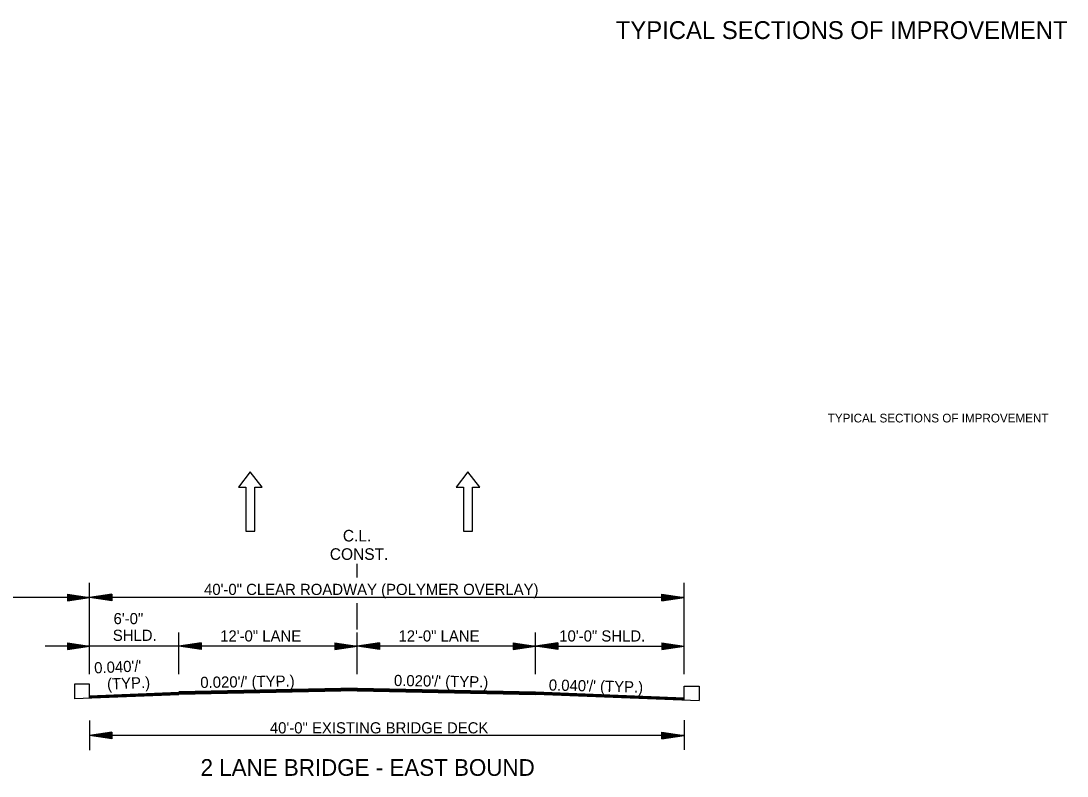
# Model space of a CAD drawing. Extents: x 550980 to 1930787, y -1972975 to 596640.
# Drawn here: x 551842 to 552546, y -1962178 to -1961670 of the extents above; entities that cross this region are included whole.
import ezdxf

# ---------------------------------------------------------------- set-up
doc = ezdxf.new("R2010")
doc.units = 0
for name, color, linetype in [('R_Border', 7, 'Continuous'), ('R_Draft', 7, 'Continuous'), ('S_AREA_CALC', 7, 'Continuous')]:
    doc.layers.add(name, color=color, linetype=linetype)

msp = doc.modelspace()

# ---------------------------------------------------------------- linework, layer by layer
at = {"layer": 'R_Border'}
for p, q in [((551878.08, -1962116.31), (551878.08, -1962126.13)), ((551888.24, -1962116.31), (551878.08, -1962116.31)), ((551888.24, -1962125.72), (551888.24, -1962116.31)), ((552288.24, -1962126.92), (552288.24, -1962117.51)), ((552288.24, -1962117.51), (552298.41, -1962117.51)), ((552298.41, -1962117.51), (552298.41, -1962127.33))]:
    msp.add_line(p, q, dxfattribs=at)
for points in [[(552004.34, -1961983.77), (551996.34, -1961973.39), (551988.34, -1961983.77), (551993.34, -1961983.77), (551993.34, -1962013.2), (551999.34, -1962013.2), (551999.34, -1961983.77)], [(552150.79, -1961983.77), (552142.79, -1961973.39), (552134.79, -1961983.77), (552139.79, -1961983.77), (552139.79, -1962013.2), (552145.79, -1962013.2), (552145.79, -1961983.77)]]:
    msp.add_lwpolyline(points, close=True, dxfattribs=at)
at = {"layer": 'R_Draft'}
for p, q in [((552068.24, -1962044.46), (552068.24, -1962035.16)), ((551888.24, -1962109.47), (551888.24, -1962047.98)), ((552288.24, -1962109.47), (552288.24, -1962047.98)), ((551873.24, -1962055.63), (551888.24, -1962057.88)), ((551873.24, -1962055.63), (551873.24, -1962060.13)), ((551903.24, -1962055.63), (551888.24, -1962057.88)), ((551903.24, -1962055.63), (551903.24, -1962060.13)), ((552273.24, -1962055.63), (552288.24, -1962057.88)), ((552273.24, -1962060.13), (552273.24, -1962055.63)), ((551888.24, -1962057.88), (551548.24, -1962057.88)), ((551873.24, -1962056), (551885.74, -1962057.88)), ((551873.24, -1962056.38), (551883.16, -1962057.88)), ((551873.24, -1962056.76), (551880.66, -1962057.88)), ((551873.24, -1962057.15), (551878.12, -1962057.88)), ((551873.24, -1962057.52), (551875.61, -1962057.88)), ((551873.24, -1962060.13), (551888.24, -1962057.88)), ((551873.24, -1962058.61), (551878.12, -1962057.88)), ((551873.24, -1962059.37), (551883.16, -1962057.88)), ((551873.24, -1962059.75), (551885.74, -1962057.88)), ((551873.24, -1962058.99), (551880.66, -1962057.88)), ((551873.24, -1962058.23), (551875.61, -1962057.88)), ((552288.24, -1962057.88), (551888.24, -1962057.88)), ((551903.24, -1962060.13), (551888.24, -1962057.88)), ((551903.24, -1962056), (551890.75, -1962057.88)), ((551903.24, -1962059.75), (551890.75, -1962057.88)), ((551903.24, -1962056.38), (551893.33, -1962057.88)), ((551903.24, -1962059.37), (551893.33, -1962057.88)), ((551903.24, -1962056.76), (551895.83, -1962057.88)), ((551903.24, -1962058.99), (551895.83, -1962057.88)), ((551903.24, -1962057.15), (551898.37, -1962057.88)), ((551903.24, -1962058.61), (551898.37, -1962057.88)), ((551903.24, -1962057.52), (551900.87, -1962057.88)), ((551903.24, -1962058.23), (551900.87, -1962057.88)), ((552258.24, -1962057.88), (551978.24, -1962057.88)), ((552068.24, -1962079.4), (552068.24, -1962061.64)), ((552273.24, -1962056), (552285.74, -1962057.88)), ((552273.24, -1962056.38), (552283.16, -1962057.88)), ((552273.24, -1962056.76), (552280.66, -1962057.88)), ((552273.24, -1962057.14), (552278.12, -1962057.88)), ((552273.24, -1962057.52), (552275.61, -1962057.88)), ((552273.24, -1962060.13), (552288.24, -1962057.88)), ((552273.24, -1962058.6), (552278.12, -1962057.88)), ((552273.24, -1962059.37), (552283.16, -1962057.88)), ((552273.24, -1962059.75), (552285.74, -1962057.88)), ((552273.24, -1962058.99), (552280.66, -1962057.88)), ((552273.24, -1962058.23), (552275.61, -1962057.88)), ((551948.24, -1962109.47), (551948.24, -1962081.52)), ((552068.24, -1962109.47), (552068.24, -1962081.52)), ((552188.24, -1962109.47), (552188.24, -1962081.52)), ((551888.24, -1962090.71), (551858.24, -1962090.71)), ((551873.24, -1962088.46), (551888.24, -1962090.71)), ((551873.24, -1962088.46), (551873.24, -1962092.96)), ((551873.24, -1962088.84), (551885.74, -1962090.71)), ((551873.24, -1962089.22), (551883.16, -1962090.71)), ((551873.24, -1962089.59), (551880.66, -1962090.71)), ((551873.24, -1962089.98), (551878.12, -1962090.71)), ((551873.24, -1962090.36), (551875.61, -1962090.71)), ((551873.24, -1962092.96), (551888.24, -1962090.71)), ((551873.24, -1962091.45), (551878.12, -1962090.71)), ((551873.24, -1962092.2), (551883.16, -1962090.71)), ((551873.24, -1962092.59), (551885.74, -1962090.71)), ((551873.24, -1962091.83), (551880.66, -1962090.71)), ((551873.24, -1962091.06), (551875.61, -1962090.71)), ((551948.24, -1962090.71), (551888.24, -1962090.71)), ((551963.24, -1962088.46), (551948.24, -1962090.71)), ((552068.24, -1962090.71), (551948.24, -1962090.71)), ((551963.24, -1962092.96), (551948.24, -1962090.71)), ((551963.24, -1962088.84), (551950.75, -1962090.71)), ((551963.24, -1962092.59), (551950.75, -1962090.71)), ((551963.24, -1962089.22), (551953.33, -1962090.71)), ((551963.24, -1962092.2), (551953.33, -1962090.71)), ((551963.24, -1962089.59), (551955.83, -1962090.71)), ((551963.24, -1962091.83), (551955.83, -1962090.71)), ((551963.24, -1962089.98), (551958.37, -1962090.71)), ((551963.24, -1962091.45), (551958.37, -1962090.71)), ((551963.24, -1962090.36), (551960.87, -1962090.71)), ((551963.24, -1962091.06), (551960.87, -1962090.71)), ((551963.24, -1962088.46), (551963.24, -1962092.96)), ((552053.24, -1962088.46), (552068.24, -1962090.71)), ((552053.24, -1962088.46), (552053.24, -1962092.96)), ((552053.24, -1962088.84), (552065.74, -1962090.71)), ((552053.24, -1962089.22), (552063.16, -1962090.71)), ((552053.24, -1962089.59), (552060.66, -1962090.71)), ((552053.24, -1962089.98), (552058.12, -1962090.71)), ((552053.24, -1962090.36), (552055.61, -1962090.71)), ((552053.24, -1962092.96), (552068.24, -1962090.71)), ((552053.24, -1962091.45), (552058.12, -1962090.71)), ((552053.24, -1962092.2), (552063.16, -1962090.71)), ((552053.24, -1962092.59), (552065.74, -1962090.71)), ((552053.24, -1962091.83), (552060.66, -1962090.71)), ((552053.24, -1962091.06), (552055.61, -1962090.71)), ((552083.24, -1962088.46), (552068.24, -1962090.71)), ((552188.24, -1962090.71), (552068.24, -1962090.71)), ((552083.24, -1962092.96), (552068.24, -1962090.71)), ((552083.24, -1962088.84), (552070.75, -1962090.71)), ((552083.24, -1962092.59), (552070.75, -1962090.71)), ((552083.24, -1962089.22), (552073.33, -1962090.71)), ((552083.24, -1962092.2), (552073.33, -1962090.71)), ((552083.24, -1962089.59), (552075.83, -1962090.71)), ((552083.24, -1962091.83), (552075.83, -1962090.71)), ((552083.24, -1962089.98), (552078.37, -1962090.71)), ((552083.24, -1962091.45), (552078.37, -1962090.71)), ((552083.24, -1962090.36), (552080.87, -1962090.71)), ((552083.24, -1962091.06), (552080.87, -1962090.71)), ((552083.24, -1962088.46), (552083.24, -1962092.96)), ((552173.24, -1962088.46), (552188.24, -1962090.71)), ((552173.24, -1962088.46), (552173.24, -1962092.96)), ((552173.24, -1962088.84), (552185.74, -1962090.71)), ((552173.24, -1962089.22), (552183.16, -1962090.71)), ((552173.24, -1962089.59), (552180.66, -1962090.71)), ((552173.24, -1962089.98), (552178.12, -1962090.71)), ((552173.24, -1962090.36), (552175.61, -1962090.71)), ((552173.24, -1962092.96), (552188.24, -1962090.71)), ((552173.24, -1962091.45), (552178.12, -1962090.71)), ((552173.24, -1962092.2), (552183.16, -1962090.71)), ((552173.24, -1962092.59), (552185.74, -1962090.71)), ((552173.24, -1962091.83), (552180.66, -1962090.71)), ((552173.24, -1962091.06), (552175.61, -1962090.71)), ((552203.24, -1962088.46), (552188.24, -1962090.71)), ((552188.24, -1962090.71), (552288.24, -1962090.71)), ((552203.24, -1962092.96), (552188.24, -1962090.71)), ((552203.24, -1962088.84), (552190.75, -1962090.71)), ((552203.24, -1962092.59), (552190.75, -1962090.71)), ((552203.24, -1962089.22), (552193.33, -1962090.71)), ((552203.24, -1962092.2), (552193.33, -1962090.71)), ((552203.24, -1962089.59), (552195.83, -1962090.71)), ((552203.24, -1962091.83), (552195.83, -1962090.71)), ((552203.24, -1962089.98), (552198.37, -1962090.71)), ((552203.24, -1962091.45), (552198.37, -1962090.71)), ((552203.24, -1962090.36), (552200.87, -1962090.71)), ((552203.24, -1962091.06), (552200.87, -1962090.71)), ((552203.24, -1962088.46), (552203.24, -1962092.96)), ((552273.24, -1962088.46), (552288.24, -1962090.71)), ((552273.24, -1962088.46), (552273.24, -1962092.96)), ((552273.24, -1962088.84), (552285.74, -1962090.71)), ((552273.24, -1962089.22), (552283.16, -1962090.71)), ((552273.24, -1962089.59), (552280.66, -1962090.71)), ((552273.24, -1962089.98), (552278.12, -1962090.71)), ((552273.24, -1962090.36), (552275.61, -1962090.71)), ((552273.24, -1962092.96), (552288.24, -1962090.71)), ((552273.24, -1962091.45), (552278.12, -1962090.71)), ((552273.24, -1962092.2), (552283.16, -1962090.71)), ((552273.24, -1962092.59), (552285.74, -1962090.71)), ((552273.24, -1962091.83), (552280.66, -1962090.71)), ((552273.24, -1962091.06), (552275.61, -1962090.71)), ((552068.24, -1962119.02), (551948.24, -1962121.42)), ((552068.24, -1962119.02), (552188.24, -1962121.42)), ((551948.24, -1962123.32), (551878.08, -1962126.13)), ((551948.24, -1962121.82), (551888.24, -1962124.22)), ((551948.24, -1962122.12), (551888.24, -1962124.52)), ((551948.24, -1962122.42), (551888.24, -1962124.82)), ((551948.24, -1962122.72), (551888.24, -1962125.12)), ((551948.24, -1962123.02), (551888.24, -1962125.42)), ((552068.24, -1962119.32), (551948.24, -1962121.72)), ((552068.24, -1962119.62), (551948.24, -1962122.02)), ((552068.24, -1962119.92), (551948.24, -1962122.32)), ((552068.24, -1962120.22), (551948.24, -1962122.62)), ((552068.24, -1962120.52), (551948.24, -1962122.92)), ((552068.24, -1962120.69), (551948.24, -1962123.09)), ((552068.24, -1962119.32), (552188.24, -1962121.72)), ((552068.24, -1962119.62), (552188.24, -1962122.02)), ((552068.24, -1962119.92), (552188.24, -1962122.32)), ((552068.24, -1962120.22), (552188.24, -1962122.62)), ((552068.24, -1962120.52), (552188.24, -1962122.92)), ((552068.24, -1962120.69), (552188.24, -1962123.09)), ((552188.24, -1962121.42), (552288.24, -1962125.42)), ((552188.24, -1962121.72), (552288.24, -1962125.72)), ((552188.24, -1962122.02), (552288.24, -1962126.02)), ((552188.24, -1962122.32), (552288.24, -1962126.32)), ((552188.24, -1962122.62), (552288.24, -1962126.62)), ((552188.24, -1962122.92), (552298.41, -1962127.33)), ((551888.24, -1962140.68), (551888.24, -1962160.68)), ((552288.24, -1962140.43), (552288.24, -1962160.43)), ((551903.24, -1962148.43), (551888.24, -1962150.68)), ((551903.24, -1962152.93), (551888.24, -1962150.68)), ((552288.24, -1962150.68), (551888.24, -1962150.68)), ((551903.24, -1962148.8), (551890.75, -1962150.68)), ((551903.24, -1962152.55), (551890.75, -1962150.68)), ((551903.24, -1962149.19), (551893.33, -1962150.68)), ((551903.24, -1962152.17), (551893.33, -1962150.68)), ((551903.24, -1962149.56), (551895.83, -1962150.68)), ((551903.24, -1962151.8), (551895.83, -1962150.68)), ((551903.24, -1962149.95), (551898.37, -1962150.68)), ((551903.24, -1962151.41), (551898.37, -1962150.68)), ((551903.24, -1962150.33), (551900.87, -1962150.68)), ((551903.24, -1962151.03), (551900.87, -1962150.68)), ((551903.24, -1962148.43), (551903.24, -1962152.93)), ((552273.24, -1962148.43), (552288.24, -1962150.68)), ((552273.24, -1962152.93), (552273.24, -1962148.43)), ((552273.24, -1962148.8), (552285.74, -1962150.68)), ((552273.24, -1962149.19), (552283.16, -1962150.68)), ((552273.24, -1962149.56), (552280.66, -1962150.68)), ((552273.24, -1962149.94), (552278.12, -1962150.68)), ((552273.24, -1962150.33), (552275.61, -1962150.68)), ((552273.24, -1962152.93), (552288.24, -1962150.68)), ((552273.24, -1962151.41), (552278.12, -1962150.68)), ((552273.24, -1962152.17), (552283.16, -1962150.68)), ((552273.24, -1962152.55), (552285.74, -1962150.68)), ((552273.24, -1962151.8), (552280.66, -1962150.68)), ((552273.24, -1962151.03), (552275.61, -1962150.68))]:
    msp.add_line(p, q, dxfattribs=at)

# ---------------------------------------------------------------- texts
at = {"layer": 'R_Border'}
msp.add_text('TYPICAL SECTIONS OF IMPROVEMENT', height=12, rotation=360, dxfattribs=at).set_placement((552242.27, -1961682.11))
at = {"layer": 'R_Draft'}
for s, height, p in [('C.L.', 7.8, (552058.64, -1962020.22)), ('CONST.', 7.8, (552049.86, -1962032.59)), ('40\'-0" CLEAR ROADWAY (POLYMER OVERLAY)', 7.5, (551965.21, -1962056.21)), ('6\'-0"', 7.5, (551904.34, -1962075.85)), ('SHLD.', 7.5, (551903.83, -1962087.1)), ('12\'-0" LANE', 7.5, (551976.06, -1962087.54)), ('12\'-0" LANE', 7.5, (552096.06, -1962087.54)), ('10\'-0" SHLD.', 7.5, (552204.23, -1962087.54)), ('40\'-0" EXISTING BRIDGE DECK', 7.5, (552009.5, -1962149.36)), ('2 LANE BRIDGE - EAST BOUND', 11.25, (551962.89, -1962177.92))]:
    msp.add_text(s, height=height, dxfattribs=at).set_placement(p)
for s, rotation, p in [("  0.040'/'", 2.44797, (551885.9, -1962109.25)), (' (TYP.)', 2.44797, (551897.33, -1962120.02)), ("0.020'/' (TYP.)", 0.97192, (551962.77, -1962118.82)), ("0.020'/' (TYP.)", 359.02808, (552092.95, -1962117.44)), ("0.040'/' (TYP.)", 358.68162, (552197.13, -1962120.5))]:
    msp.add_text(s, height=7.5, rotation=rotation, dxfattribs=at).set_placement(p)
at = {"layer": 'S_AREA_CALC'}
msp.add_text('TYPICAL SECTIONS OF IMPROVEMENT', height=5.862, rotation=360, dxfattribs=at).set_placement((552384.89, -1961940.12))

doc.saveas('drawing.dxf')
